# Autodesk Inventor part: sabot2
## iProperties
Shininess: 64.0
Length Units: 11269
Angle Units: 11279
Time Units: 11290
Mass Units: 11283
Length Display Precision: 3
Angle Display Precision: 2
Compacted: True
Part Number: sabot2
Document SubType Name: Modeling
Created: 2005-02
Material: Par défaut
Designer: LEGERET Philippe
Density: 0.0
Volumn: 0.0
Area: 0.0
PropertySet Name: Model Information
Control State: 0
Master: False
Checked Out: False
Author: LEGERET Philippe
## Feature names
1. Extrusion1
2. Extrusion2
3. Extrusion3
4. Extrusion4
5. Extrusion5
6. Chanfrein5 [Chamfer]
7. Chanfrein6 [Chamfer]
8. Chanfrein7 [Chamfer]
9. Extrusion6
